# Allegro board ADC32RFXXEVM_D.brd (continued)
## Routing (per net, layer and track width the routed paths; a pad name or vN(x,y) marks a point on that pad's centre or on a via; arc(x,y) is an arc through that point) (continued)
V1: length 33
  TOP w0.229: U32.1 18.38,45.85 v1(18.24,46) ; U33.1 v2(18.39,42.65)
  L4_SIG w0.127: v2(18.39,42.65) 18.65,42.65 18.92,42.92 18.92,43.76 18.49,44.2 18.49,45.75 v1(18.24,46) 18.16,46 15.11,49.05 15.11,51.91 23.12,59.92 23.62,59.92 24.05,60.35 v1(24.13,60.35) 24.18,60.35 24.69,60.86 25.7,60.86 25.96,61.11 25.96,64.74 26.37,65.15 26.77,65.15 JP3.1
V2: length 32.7
  TOP w0.203: U33.5 18.03,40.59 v1(17.88,40.44)
  TOP w0.229: U32.5 v2(18.03,42.95)
  L4_SIG w0.127: JP3.3 27.05,60.35 v1(25.27,60.35) 24.92,60.35 16.79,52.22 16.79,51.26 17.63,50.42 17.63,47.73 19.27,46.09 19.27,45.02 19.62,44.66 19.62,43.37 19.38,43.13 19.38,42.04 17.88,40.54 v1(17.88,40.44) 17.65,40.67 17.65,42.27 18.03,42.65 v2(18.03,42.95)
A_IN_M: length 14.8
  TOP w0.483: J2.1 3.82,22.57 arc(4.57,22.42) 5.21,21.99 5.66,21.54 arc(6.4,21.05) 7.26,20.88 11.6,20.88 arc(13.88,21.33) C415.1
A_IN_P: length 14.8
  TOP w0.483: C414.1 13.66,24.79 13.17,24.79 arc(12.57,24.91) 12.06,25.25 5.09,32.22 arc(4.53,32.6) 3.87,32.73 J1.1
ADC_CLK: length 4.3
  BOTTOM w0.483: J5.1 3.77,42.89 arc(4.26,42.99) 4.68,43.27 4.83,43.41 arc(5.37,43.78) C28.1
ADC_CLKM: length 3.1
  TOP w0.229: U1.28 22.07,42.49 22.01,42.55 20.59,42.55 R26.1
  TOP w0.305: C430.2 20.33,42.29 R26.1
ADC_CLKP: length 3.1
  TOP w0.229: U1.27 22.07,42.99 22.01,42.93 20.49,42.93 R26.2
  TOP w0.305: R26.2 20.36,43.05 C429.2
ADC_SCLK: length 45.1
  TOP w0.127: v1(30.27,50.79) 30.27,50.3 30.17,50.2 30.17,50.01 30.16,50 30.16,48.97 30.14,48.94 30.14,48.65 29.44,47.96 29.44,47.69 U1.6
  L4_SIG w0.127: v1(30.27,50.79) 29.56,50.79 29.18,50.42 26.95,50.42 26.48,49.95 26.48,48.28 26.98,47.78 26.98,40.07 26.53,39.61 26.33,39.61 25.82,39.11 25.82,38.59 25.91,38.5 25.91,35.28 27.28,33.91 31.86,33.91 33.25,32.51 34.16,32.51 35.41,31.27 35.41,30.84 37.54,28.7 37.54,26.75 39.78,24.51 v1(39.78,24.36)
  BOTTOM w0.127: v1(39.78,24.36) 39.8,24.33 U29.2
ADC_SDIO: length 39.6
  TOP w0.127: U1.5 29.89,47.92 30.39,48.43 30.39,48.84 30.42,48.86 30.42,49.9 30.42,49.9 30.42,50.09 v1(31.35,51.02)
  L4_SIG w0.127: v1(43.21,25.35) 43.21,26.06 40.64,28.63 39.57,28.63 35.53,32.66 35.53,33.35 30.66,38.23 30.12,38.23 29.77,38.58 29.77,47.19 30.33,47.75 30.33,50 v1(31.35,51.02)
  BOTTOM w0.127: v1(43.21,25.35) 43.21,24.08 42.81,23.68 U29.3
ADC_SDO: length 43.5
  TOP w0.127: v1(26.92,48.46) 26.89,48.42 U1.11
  L4_SIG w0.127: v1(33.07,48.13) 32.81,48.13 32.8,48.15 32.17,48.15 31.04,47.02 31.04,38.48 33.53,35.99 34.04,35.99 39.57,30.45 40.03,30.45 43.71,26.77 43.71,25.12 42.11,23.52 v1(40.39,23.52)
  BOTTOM w0.127: v1(33.07,48.13) 32.81,48.13 32.8,48.15 32.02,48.15 31.48,47.61 27.7,47.61 26.92,48.39 v1(26.92,48.46) ; U29.4 40.88,23.03 v1(40.39,23.52)
ADC_SEN: length 39.4
  TOP w0.127: U1.7 28.89,47.86 29.71,48.68 v1(29.73,49.15)
  L4_SIG w0.127: v1(29.73,49.15) 29.47,48.89 29.47,48.21 28.37,47.12 28.37,38.58 28.78,38.18 29.64,38.18 30.07,37.74 30.53,37.74 32.35,35.93 32.35,34.84 35.9,31.29 35.9,30.88 36.58,30.2 37.53,30.2 38.46,29.27 38.46,28.53 38.05,28.12 38.05,26.72 40.18,24.59 40.18,24.58 40.22,24.54 40.22,24.17 39.96,23.91 39,23.91 v1(38.79,24.13)
  BOTTOM w0.127: v1(38.79,24.13) 40.54,22.38 U29.5
AIN+: length 4.1
  TOP w0.483: C1.1 T2.3 20.61,31.39 T1.1 18.83,29.65 R1.2
AIN-: length 4.1
  TOP w0.483: R11.2 T1.3 20.66,27.89 T2.1 C6.1
AINM: length 6
  TOP w0.635: 25.26,36.39 25.26,35.35 arc(25.23,34.79) 25.15,34.23 arc(24.96,33.92) 24.6,33.82 arc(24.38,33.9) 24.21,34.06 arc(23.85,34.36) 23.4,34.23 T2.4 22.29,33.11 C1.2
AINP: length 5.9
  TOP w0.635: C6.2 24.1,31.33 T2.6 25.05,32.28 arc(25.85,33.48) 26.13,34.89 26.13,36.53
B_IN_M: length 14.7
  TOP w0.483: J4.1 4.15,53.05 arc(4.6,53.14) 4.98,53.39 11.56,59.97 arc(12.34,60.5) 13.27,60.68 13.69,60.68 C417.1
B_IN_P: length 14.7
  TOP w0.483: C416.1 14.74,63.88 arc(14.17,64.26) 13.5,64.39 6.81,64.39 arc(6.2,64.27) 5.67,63.92 5.37,63.61 arc(4.92,63.31) 4.39,63.21 J3.1
BIN+: length 4.1
  TOP w0.483: C12.1 T4.1 T3.3 18.3,56.35 R23.2
BIN-: length 3.3
  TOP w0.483: T4.3 T3.1 R13.2
BINM: length 5.9
  TOP w0.635: T4.6 23.59,51.07 24.07,51.07 24.42,51.42 arc(25.09,51.49) 25.45,50.92 25.45,49.2
  TOP w0.762: C12.2 T4.6
BINP: length 6
  TOP w0.635: T4.4 24.65,53.58 25.71,52.52 arc(26.18,51.82) 26.34,51.01 26.34,49.05
  TOP w0.762: C7.2 T4.4
CE: length 18.4
  L6_PWR w0.305: JP2.2 34.47,64.74 38.48,64.74 39.57,63.65 48.62,63.65 v1(48.67,63.7)
  BOTTOM w0.305: v1(48.67,63.7) 48.66,63.69 U30.1
CLK-IN: length 4.2
  BOTTOM w0.483: R56.1 T6.6 62.58,62.81 R59.1 R57.2
CLK_LAO_0M: length 39.8
  BOTTOM w0.165: 123.44,52.01 123.51,52.07 127.47,52.07 127.64,51.9 127.64,51.56
  BOTTOM w0.203: 90.47,52.66 90.44,52.69 R79.2
  BOTTOM w0.229: 90.47,52.66 91.16,51.97 112.69,51.97 114.52,50.14 116.48,50.14 118.35,52.01 123.44,52.01
CLK_LAO_0P: length 39.8
  BOTTOM w0.165: 123.44,52.39 123.51,52.32 127.47,52.32 127.64,52.49 127.64,52.83
  BOTTOM w0.203: R75.2 90.69,52.98 90.73,52.94
  BOTTOM w0.229: 123.44,52.39 118.19,52.39 116.33,50.52 114.68,50.52 112.85,52.35 93.12,52.35 92.76,52.7 92.29,52.7 91.93,52.35 91.32,52.35 90.73,52.94
CLKIN1_N: length 6.5
  BOTTOM w0.229: C74.2 72.79,64.64 72.8,64.66 72.86,64.66 72.89,64.69 73.58,64.69 C75.2 73.71,64.72 74.47,63.96 76.65,63.96 77.1,63.51 77.1,62.87 77.16,62.81 U3.35
CLKIN1_P: length 6.1
  BOTTOM w0.229: U3.34 76.66,62.81 76.72,62.87 76.72,63.35 76.49,63.58 74.31,63.58 73.62,64.27 72.96,64.27 72.77,64.08 C73.2
CLKINN: length 4.4
  BOTTOM w0.483: C74.1 70.51,64.64 R60.2 69.8,65.35 T6.3
CLKINP: length 5.4
  BOTTOM w0.483: R56.2 T6.1 69.44,62.81 R60.1 70.43,63.8 R55.1 71.4,63.88 C73.1
CLKLA_0M: length 6.3
  BOTTOM w0.203: 89.67,53.12 89.62,53.12 89.05,53.7
  BOTTOM w0.229: U3.63 85.37,54.1 85.43,54.16 85.95,54.16 86.1,54.31 87.4,54.31 87.73,53.98 88.08,53.98 88.42,54.31 88.85,54.31 89.08,54.07 89.08,53.73 89.05,53.7
CLKLA_0P: length 6.3
  BOTTOM w0.203: R77.1 90.26,53.78 R75.1
  BOTTOM w0.229: R77.1 89.66,54.31 89.38,54.31 89.01,54.69 85.94,54.69 85.8,54.54 85.43,54.54 85.37,54.6 U3.62
CLKM: length 53.5
  TOP w0.229: v1(36.3,56.41) 36.3,58.18 34.75,59.73 33.93,59.73 33.71,59.5 v1(33.71,58.93)
  BOTTOM w0.229: v1(36.3,56.41) 36.39,56.41 36.93,55.87 36.93,54.71 37.2,54.44 37.76,54.44 37.97,54.24 37.97,53.68 43.55,48.09 43.83,48.09 43.97,48.23 44.25,48.23 44.45,48.03 44.45,47.74 44.32,47.61 44.32,47.33 45.09,46.56 73.42,46.56 73.62,46.76 73.62,46.97 73.82,47.17 74.11,47.17 74.31,46.97 74.31,46.76 74.51,46.56 75.44,46.56 75.86,46.98 75.86,47.83 75.67,48.02 C9.2
CLKP: length 53.5
  TOP w0.229: v1(36.42,55.68) 36.77,56.02 36.77,56.61 36.68,56.7 36.68,58.34 34.91,60.11 33.93,60.11 33.71,60.34 v1(33.73,60.91)
  BOTTOM w0.229: v1(36.42,55.68) 36.55,55.55 36.55,54.55 44.93,46.18 75.6,46.18 76.24,46.82 76.24,47.83 76.43,48.02 C8.2
CP1: length 37.8
  L4_SIG w0.305: v1(104.6,62.76) 104.34,62.76 102.84,64.26 96.6,64.26 95.61,65.25 94.39,65.25 93.8,64.67 82.91,64.67 80.98,62.74 78.49,62.74 77.57,63.65 74.76,63.65 74.22,63.11 74.22,61.62 73.71,61.11 v1(73.25,61.11)
  BOTTOM w0.305: U3.32 73.26,61.11 v1(73.25,61.11)
  vias: v1(105.36,62.76)
CP2: length 5.6
  BOTTOM w0.305: U3.46 82.66,62.46 82.97,62.76 85.01,62.76 85.37,62.41 C72.1 87.35,62.41 C71.1
CPOUT: length 15
  TOP w0.229: v1(47.14,57.35) 50.72,60.93 v1(50.72,66.32)
  BOTTOM w0.229: v1(50.72,66.32) 50.67,66.37 C395.1 49.15,66.37 R182.1 ; U30.12 45.16,57.64 45.44,57.35 v1(47.14,57.35)
DA0_M: length 2.8
  TOP w0.229: U1.62 32.59,41.94 33.49,41.94 33.62,41.81 35.04,41.81 C14.1
DA0_P: length 2.8
  TOP w0.229: C13.1 34.99,41.43 33.46,41.43 33.33,41.55 32.6,41.55 U1.61
DA0M: length 106.8
  TOP w0.229: v1(133.99,43.94) 133.99,44.07 134.29,44.37 134.78,44.37 135.23,44.83 135.23,45.5 134.52,46.2 130.88,46.2 126.31,41.63 124.66,41.63 121.43,38.4 43.66,38.4 40.28,41.78 36,41.78 C14.2
DA0P: length 106.8
  TOP w0.229: C13.2 36,41.4 40.13,41.4 43.5,38.02 121.59,38.02 124.82,41.25 126.47,41.25 127.15,41.93 127.61,41.93 127.91,42.24 127.91,42.7 129.79,44.57 130.07,44.57 130.29,44.34 130.58,44.34 130.78,44.55 130.78,44.83 130.55,45.05 130.55,45.34 131.04,45.82 134.37,45.82 134.85,45.34 134.85,44.98 134.62,44.75 134.29,44.75 133.99,45.06 v1(133.99,45.21)
DA1_M: length 3.1
  TOP w0.229: U1.59 32.79,40.49 32.85,40.43 33.79,40.43 34.58,39.64 35.03,39.64 C16.1
DA1_P: length 3.1
  TOP w0.229: C15.1 35,39.26 34.42,39.26 33.63,40.05 32.83,40.05 32.77,39.99 U1.58
DA1M: length 108.3
  TOP w0.229: C16.2 36,39.62 39.12,39.62 42.45,36.3 122.17,36.3 125.39,39.52 127.99,39.52 131.69,43.23 134.18,43.23 134.74,43.79 136.15,43.79 136.6,43.34 136.6,42.33 136.15,41.88 135.73,41.88 v1(135.25,41.4)
DA1P: length 108.2
  TOP w0.229: v1(135.25,42.67) 135.67,42.26 135.99,42.26 136.22,42.49 136.22,43.18 135.99,43.41 134.9,43.41 134.34,42.85 131.85,42.85 131.57,42.57 131.57,42.28 131.67,42.19 131.67,41.9 131.47,41.7 131.18,41.7 131.09,41.8 130.8,41.8 129.18,40.18 129.18,39.9 129.29,39.79 129.29,39.5 129.09,39.3 128.81,39.3 128.7,39.41 128.41,39.41 128.14,39.14 125.55,39.14 122.33,35.92 42.29,35.92 38.96,39.24 36,39.24 C15.2
DA2_M: length 3.3
  TOP w0.229: C18.1 35.06,37.51 34.81,37.51 33.39,38.93 32.85,38.93 32.8,38.99 U1.56
DA2_P: length 3.4
  TOP w0.229: C17.1 34.99,37.11 34.67,37.11 33.23,38.55 32.78,38.55 32.72,38.49 U1.55
DA2M: length 106.4
  TOP w0.229: v1(133.99,38.86) 133.99,39.02 134.28,39.32 134.69,39.32 135.15,39.77 135.15,40.55 134.27,41.43 132.2,41.43 128.06,37.29 125.75,37.29 122.78,34.32 41.36,34.32 38.21,37.47 36,37.47 C18.2
DA2P: length 106.4
  TOP w0.229: C17.2 36,37.08 38.05,37.08 41.2,33.93 122.94,33.93 125.91,36.91 126.45,36.91 126.76,36.6 127.14,36.6 127.45,36.91 128.22,36.91 130.98,39.67 131.27,39.67 131.5,39.43 131.79,39.43 131.99,39.64 131.99,39.92 131.75,40.16 131.75,40.44 132.36,41.05 134.11,41.05 134.77,40.39 134.77,39.93 134.54,39.7 134.21,39.7 133.99,39.93 v1(133.99,40.13)
DA3_M: length 5.3
  TOP w0.229: C20.1 35.01,35.31 34.09,35.31 33.66,35.74 33.66,36.02 33.79,36.15 33.79,36.47 33.56,36.7 32.69,36.7 31.84,37.56 31.84,37.79 U1.54
DA3_P: length 5.3
  TOP w0.229: U1.53 31.46,37.77 31.46,37.4 33.93,34.92 35.01,34.92 C19.1
DA3M: length 107.2
  TOP w0.229: C20.2 36,35.31 37.11,35.31 40.24,32.18 130.72,32.18 131.08,32.54 131.41,32.54 131.76,32.18 133.43,32.18 135.28,34.04 135.28,34.32 135.07,34.53 135.07,34.82 135.27,35.02 135.56,35.02 135.77,34.81 136.05,34.81 136.4,35.15 136.4,36.54 136.17,36.77 135.7,36.77 v1(135.25,36.32)
DA3P: length 107.3
  TOP w0.229: C19.2 36,34.92 36.96,34.92 40.08,31.8 133.58,31.8 136.78,35 136.78,36.7 136.33,37.15 135.7,37.15 v1(135.25,37.59)
DB0_M: length 2.8
  TOP w0.229: U1.65 32.84,43.49 32.9,43.54 35.03,43.54 C22.1
DB0_P: length 2.8
  TOP w0.229: U1.66 32.85,43.99 32.91,43.93 35,43.93 C21.1
DB0M: length 103.9
  TOP w0.229: v1(135.25,46.48) 134.8,46.94 129.59,46.94 126.03,43.38 123.98,43.38 120.73,40.13 44.45,40.13 41.02,43.56 36,43.56 C22.2
DB0P: length 103.9
  TOP w0.229: v1(135.25,47.75) 134.82,47.32 129.43,47.32 125.88,43.76 123.82,43.76 120.57,40.51 44.61,40.51 41.18,43.94 36,43.94 C21.2
DB1_M: length 3.1
  TOP w0.229: U1.68 32.84,44.99 32.9,45.05 33.74,45.05 34.42,45.72 35.01,45.72 C24.1
DB1_P: length 3.1
  TOP w0.229: U1.69 32.82,45.49 32.88,45.43 33.59,45.43 34.26,46.1 35.01,46.1 C23.1
DB1M: length 102.8
  TOP w0.229: v1(132.72,51.56) 132.72,51.64 132.33,52.02 129.72,52.02 119.86,42.16 45.49,42.16 41.94,45.72 36,45.72 C24.2
DB1P: length 102.7
  TOP w0.229: C23.2 36,46.1 42.09,46.1 45.65,42.55 119.7,42.55 129.56,52.4 132.33,52.4 132.72,52.78 v1(132.72,52.83)
DB2_M: length 3.3
  TOP w0.229: C27.1 35.04,47.85 34.6,47.85 33.3,46.55 32.84,46.55 32.77,46.49 U1.71
DB2_P: length 3.3
  TOP w0.229: C26.1 34.99,48.23 34.44,48.23 33.14,46.94 32.82,46.94 32.77,46.99 U1.72
DB2M: length 106.2
  TOP w0.229: v1(135.25,51.56) 135.25,51.74 134.95,52.04 134.09,52.04 133.48,52.65 133.48,53.14 132.89,53.72 128.81,53.72 119.39,44.3 46.74,44.3 43.15,47.88 36,47.88 C27.2
DB2P: length 106.2
  TOP w0.229: C26.2 36,48.26 43.31,48.26 46.89,44.68 119.23,44.68 128.65,54.1 133.05,54.1 133.86,53.29 133.86,52.81 134.24,52.43 135.03,52.43 135.25,52.65 v1(135.25,52.83)
DB3_M: length 5.3
  TOP w0.229: C31.1 35.01,50.04 33.91,50.04 33.66,49.78 33.66,49.38 33.76,49.28 33.76,48.94 33.48,48.67 32.54,48.67 31.83,47.96 31.83,47.69 U1.1
DB3_P: length 5.3
  TOP w0.229: C30.1 35.01,50.42 33.75,50.42 31.45,48.11 31.45,47.7 U1.2
DB3M: length 106
  TOP w0.229: v1(135.25,56.64) 135.25,56.82 134.98,57.1 131.96,57.1 131.68,56.82 129.01,56.82 118.36,46.18 47.9,46.18 44.02,50.06 36.03,50.06 C31.2
DB3P: length 105.9
  TOP w0.229: v1(135.25,57.91) 135.25,57.71 135.03,57.48 131.8,57.48 131.52,57.2 128.85,57.2 118.21,46.56 48.06,46.56 44.18,50.44 35.98,50.44 C30.2
DCLKOUT10N: length 4.2
  BOTTOM w0.229: C171.1 88.09,58.14 87.73,58.14 R151.1 87.15,58.17 84.96,58.17 84.9,58.11 U3.55
DCLKOUT10P: length 4.1
  BOTTOM w0.229: U3.54 84.9,58.61 84.99,58.52 87.2,58.52 R152.1 87.73,58.5 88.09,58.5 C170.1
FMC_CTRL1: length 175.1
  L4_SIG w0.127: v1(132.72,27.43) 132.72,27.28 132.16,26.72 123.47,26.72 122.68,25.93 122.68,7.54 120.68,5.54 119.2,5.54 113.84,10.9 98.91,10.9 98.02,10.01 97.35,10.01 97.33,10.02 85.38,10.02 85.26,10.15 84.45,10.15 79.08,15.52 71.65,15.52 71.01,16.16 69.41,16.16 69.1,16.47 66.03,16.47 65.56,16 54.64,16 53.94,16.69 50.5,16.69 48.74,14.94 31.93,14.94 29.46,17.4 29.46,19.41 28.79,20.08 28.79,25.36 26.29,27.86 26.29,31.45 23.16,34.57 22.46,34.57 21.68,35.35 21.68,38.79 23.48,40.6 23.9,40.6 24.19,40.89 24.19,44.26 23.9,44.55 23.31,44.55 22.7,45.16 22.43,45.16 18.58,49.01 18.58,49.06 18.49,49.15 18.49,52.12 v1(18.06,52.55)
  BOTTOM w0.229: R165.1 v1(18.06,52.55)
FMC_CTRL2: length 172.7
  L4_SIG w0.127: v1(17.25,51.74) 18.06,50.93 18.06,47.98 19.96,46.08 19.96,40.92 18.75,39.7 18.75,35.23 19.31,34.66 21.65,34.66 24.47,31.84 25.1,31.84 25.84,31.1 25.84,26.73 28.07,24.5 28.07,22.39 27.84,22.15 27.84,18.31 31.6,14.55 52.12,14.55 52.57,15 79,15 84.21,9.79 84.54,9.79 85.3,9.03 102.73,9.03 104.06,10.36 113.56,10.36 118.97,4.95 120.8,4.95 123.16,7.31 123.16,24.35 124.23,25.43 131.98,25.43 v1(132.72,26.16)
  BOTTOM w0.229: 18.16,50.83 v1(17.25,51.74)
FPGA_JESD_CLKM: length 55.2
  BOTTOM w0.165: 123.44,50.75 123.5,50.81 129.22,50.81 129.66,51.25 129.66,54.32 129.95,54.61 131.28,54.61 131.44,54.44 J10.D5
  BOTTOM w0.229: 123.44,50.75 122.97,50.75 118.39,46.18 84.89,46.18 83.49,47.57 83.49,48.25 C69.2
FPGA_JESD_CLKP: length 55.2
  BOTTOM w0.165: 123.44,51.13 123.46,51.13 123.53,51.06 129.11,51.06 129.41,51.35 129.41,54.43 129.84,54.86 131.28,54.86 131.44,55.03 J10.D4
  BOTTOM w0.229: 123.44,51.13 122.81,51.13 121.92,50.25 121.62,50.25 121.26,49.89 121.26,49.58 118.24,46.56 86.85,46.56 86.65,46.76 86.65,46.81 86.45,47.02 86.16,47.02 85.96,46.81 85.96,46.76 85.76,46.56 85.04,46.56 83.87,47.73 83.87,48.26 C67.2
FPGA_JESD_SYSREFM: length 50.6
  BOTTOM w0.165: 123.44,48.2 123.46,48.2 123.53,48.26 127.47,48.26 127.64,48.09 127.64,47.75
  BOTTOM w0.203: R49.2 81.21,47.46 81.21,46.47 83.39,44.3 119.35,44.3 123.25,48.2
  BOTTOM w0.229: 123.44,48.2 123.25,48.2
FPGA_JESD_SYSREFP: length 50.6
  BOTTOM w0.165: 123.44,48.58 123.46,48.58 123.53,48.52 127.13,48.52 127.64,49.02
  BOTTOM w0.203: R48.2 81.57,47.46 81.57,46.62 81.91,46.27 82.17,46.27 82.27,46.38 82.52,46.38 82.7,46.2 82.7,45.95 82.6,45.84 82.6,45.59 83.54,44.65 117.99,44.65 118.19,44.86 118.65,44.86 118.85,44.65 119.21,44.65 122.89,48.33 122.89,48.35 123.1,48.57 123.2,48.57 123.22,48.58 123.25,48.58
  BOTTOM w0.229: 123.44,48.58 123.25,48.58
GPIO1: length 49.9
  TOP w0.127: v1(22.02,47.52) 22.56,46.99 U1.19
  L4_SIG w0.127: TP3.1 53.11,31.8 53.11,32.71 49.88,35.94 49.25,35.94 41.33,43.87 40.79,43.87 34.34,50.32 34.01,50.32 32.79,51.54 27.68,51.54 27.5,51.36 26.75,51.36 25.1,49.71 25.1,48.49 24.13,47.52 v1(22.02,47.52)
GPIO2: length 30.3
  TOP w0.127: U1.63 v1(33.77,42.49)
  L4_SIG w0.127: v1(33.77,42.49) 33.77,42.81 34.26,43.31 41.15,43.31 49.1,35.36 49.1,35.03 52.81,31.32 TP7.1
GTXCLKM: length 4.1
  BOTTOM w0.203: 83.27,49.9 83.5,50.12 83.5,51.07 83.24,51.33 83.24,51.87 83.16,51.94 U3.2 ; C69.1 83.3,49.11 ; 83.3,49.82 R52.1
  BOTTOM w0.229: 83.27,49.9 83.3,49.87 83.3,49.11
GTXCLKP: length 4.1
  BOTTOM w0.203: 84.06,49.82 R53.1 ; C67.1 84.06,49.11 ; U3.1 83.66,51.94 83.59,51.87 83.59,51.48 83.86,51.22 83.86,50.12 84.08,49.9
  BOTTOM w0.229: 84.08,49.9 84.06,49.87 84.06,49.11
JESD_SYSREFM: length 5.2
  BOTTOM w0.203: U3.4 82.16,51.94 82.24,51.87 82.24,51.58 81.23,50.58 81.23,49.35 80.99,49.11 ; R49.1 81.01,48.32 ; 81.01,49.03 R50.1
  BOTTOM w0.229: 80.99,49.11 81.01,49.08 81.01,48.32
JESD_SYSREFP: length 5.2
  BOTTOM w0.203: 81.8,49.11 81.58,49.32 81.58,50.43 82.59,51.43 82.59,51.87 82.66,51.94 U3.3 ; 81.77,49.03 R51.1 ; R48.1 81.77,48.32
  BOTTOM w0.229: 81.8,49.11 81.77,49.08 81.77,48.32
LMK LOCKED:
  vias: v1(55.78,55.65)
LMK_CLKIN: length 4.8
  BOTTOM w0.483: R57.1 R58.1 56.16,62.79 J7.1
LMK_CSB: length 78.9
  L4_SIG w0.127: v1(73.91,50.8) 74.42,50.29 74.42,47.32 74.14,47.04 74.14,40.03 75.22,38.95 75.22,26.1 75.51,25.81 75.51,24.05 71.48,20.02 46.96,20.02 46.44,19.49 44.51,19.49 44.13,19.88 35.31,19.88 34.9,19.47 v1(32.73,19.47)
  BOTTOM w0.127: v1(73.91,50.8) 73.6,51.12 73.6,53.78 73.92,54.1 U3.18 ; U5.6 v1(32.73,19.47)
LMK_SCLK: length 111.9
  TOP w0.127: v1(37.31,25.37) 37.31,24.92 36.7,24.31 34.82,24.31 33.23,22.72 v1(32.78,22.72)
  L4_SIG w0.127: v1(43.13,57.23) 43.13,56.67 43.54,56.26 45.09,56.26 46.52,54.83 46.52,54.43 46.78,54.17 47.28,54.17 47.89,53.56 48.94,53.56 49.22,53.28 49.59,53.28 49.73,53.42 52.22,53.42 54.84,50.8 v1(72.03,50.8) 72.03,50.27 71.49,49.72 71.49,27.52 69.65,25.68 54.71,25.68 50.24,21.21 46.36,21.21 45.9,21.67 39.24,21.67 37.31,23.6 v1(37.31,25.37)
  BOTTOM w0.127: U3.19 74.06,54.6 73.23,53.77 73.23,51.44 72.67,50.88 72.11,50.88 v1(72.03,50.8) ; U5.1 v1(32.78,22.72) ; v1(43.13,57.23) 43.16,57.26 U30.16 ; U29.13 36.78,24.33 37.31,24.87 v1(37.31,25.37)
LMK_SDIO: length 116.7
  L4_SIG w0.127: v1(42.65,57.63) 42.65,58.24 43.71,59.31 44.86,59.31 45.29,58.88 45.29,57.91 46.37,56.83 46.37,55.66 46.98,55.05 47.15,55.05 47.43,54.77 47.43,54.55 48.06,53.92 48.98,53.92 49.22,54.17 49.59,54.17 49.83,53.92 52.32,53.92 54.89,51.36 v1(72.47,51.36) 72.54,51.28 72.54,49.96 71.98,49.4 71.98,38 72.47,37.52 72.47,35.94 72.09,35.56 72.09,27.43 69.82,25.17 54.86,25.17 50.5,20.8 46.09,20.8 45.78,21.12 42.81,21.12 42.24,20.55 40.56,20.55 40.31,20.8 35.38,20.8 34.7,20.12 v1(33.5,20.12) 33.5,22.99 34.2,23.68 v1(34.84,23.68)
  BOTTOM w0.127: U30.17 v1(42.65,57.63) ; U3.20 73.95,55.1 72.92,54.08 72.92,51.82 v1(72.47,51.36) ; U5.5 v1(33.5,20.12) ; U29.12 v1(34.84,23.68)
LMK_SDO: length 82.9
  TOP w0.127: v2(81.66,52.78) 81.66,52.45 80.29,51.08 75.29,51.08 v1(74.94,50.74)
  L4_SIG w0.127: v1(74.94,50.74) 75.67,50.01 75.67,43.63 75.68,43.62 75.68,26.56 75.95,26.29 75.95,23.67 71.75,19.48 47.35,19.48 46.89,19.02 44.2,19.02 43.73,19.49 41.73,19.49 41.59,19.35 35.86,19.35 v1(33.38,16.87)
  BOTTOM w0.127: U5.10 v1(33.38,16.87)
LMX_CLKB: length 23.1
  BOTTOM w0.483: R191.2 61.49,59.44 arc(61.4,58.97) 61.14,58.58 arc(60.82,58.37) 60.45,58.29 54.13,58.29 arc(52.86,58.04) 51.78,57.32 48.92,54.45 arc(48.13,53.93) 47.21,53.75 R192.2 43.38,54.38 C412.2
LMX_CLKM: length 30.1
  TOP w0.229: v1(17.02,44.98) 17.68,44.98 U32.3
  BOTTOM w0.229: v1(17.02,44.98) 17.02,44.07 16.79,43.84 16.21,43.84 15.44,44.6 15.44,44.88 15.59,45.02 15.59,45.35 15.44,45.49 15.44,45.75 15.72,46.02 15.88,46.02 16.21,45.68 16.37,45.68 16.5,45.81 16.5,46.14 16.33,46.31 16.33,46.63 16.74,47.04 19.2,47.04 31.14,58.98 31.42,58.98 31.69,59.25 31.69,59.52 31.89,59.73 33.12,59.73 33.32,59.54 C410.2
LMX_CLKP: length 30.1
  TOP w0.229: v1(17.02,42.32) 17.68,42.32 U33.3
  BOTTOM w0.229: C431.1 33.32,60.3 33.12,60.11 31.73,60.11 19.04,47.42 16.58,47.42 15.06,45.9 15.06,44.44 16.05,43.46 16.79,43.46 17.02,43.23 v1(17.02,42.32)
LMX_CSB: length 71.3
  L4_SIG w0.127: v1(30.05,17.53) 29.87,17.7 29.87,19.63 30.52,20.29 30.52,24.01 30.07,24.46 30.07,25.98 27.74,28.32 27.74,32.87 25.5,35.1 25.5,39.22 25.7,39.42 25.7,45.52 25.1,46.13 22.5,46.13 19.2,49.43 19.2,50.36 20.09,51.26 21.21,51.26 21.67,50.8 22.17,50.8 24.89,53.52 25.35,53.52 26.4,54.57 27.78,54.57 28.07,54.28 31.04,54.28 31.43,54.67 32.3,54.67 32.49,54.48 36.65,54.48 37.17,55 37.17,55.3 37.43,55.56 38.04,55.56 38.61,56.13 38.61,56.58 37.9,57.3 37.9,57.99 39.32,59.41 v1(39.32,61.32)
  BOTTOM w0.127: U5.9 v1(30.05,17.53) ; U30.24 39.71,60.69 39.32,61.09 v1(39.32,61.32)
LMX_OSCM: length 39.6
  TOP w0.229: v1(50.4,57.81) 50.68,58.09 64.95,58.09 72.95,66.09 74.85,66.09 v1(75.08,65.86)
  BOTTOM w0.203: v1(75.08,65.86) 75.39,66.17 75.79,66.17 76.4,66.78 78.12,66.78 78.29,66.6 78.29,66.45 78.47,66.27 78.73,66.27 78.9,66.45 78.9,66.6 79.08,66.78 79.44,66.78 79.72,66.5 79.72,65.8 C418.2 ; U30.9 47.27,59.69 47.32,59.75
  BOTTOM w0.229: v1(50.4,57.81) 50.14,58.06 49.43,58.06 47.75,59.74 47.33,59.74 47.32,59.75
LMX_OSCP: length 39.6
  TOP w0.229: v1(75.08,66.78) 74.77,66.47 72.79,66.47 64.79,58.47 50.66,58.47 v1(50.4,58.73)
  BOTTOM w0.203: v1(75.08,66.78) 75.34,66.52 75.64,66.52 76.25,67.13 79.59,67.13 80.07,66.64 80.07,65.8 C419.2 ; U30.8 47.27,60.19 47.34,60.12 47.49,60.12 47.49,60.12
  BOTTOM w0.229: 47.49,60.12 47.91,60.12 49.59,58.45 50.12,58.45 v1(50.4,58.73)
LMX_SDO: length 59
  L4_SIG w0.127: v1(38.07,56.36) 37.59,56.36 36.87,55.64 36.87,55.26 36.5,54.89 32.74,54.89 32.49,55.14 31.32,55.14 30.89,54.71 28.07,54.71 27.89,54.89 26.24,54.89 25.25,53.9 24.66,53.9 22.99,52.22 20.47,52.22 18.88,50.63 18.88,49.21 22.4,45.69 22.6,45.69 23.42,44.87 24,44.87 24.49,44.38 24.49,40.21 23.9,39.61 23.66,39.61 22.76,38.71 22.76,35.49 23.22,35.03 23.65,35.03 27.28,31.39 27.28,28.35 29.72,25.91 29.72,24.05 30.08,23.69 v1(30.08,22.07)
  BOTTOM w0.127: U5.2 v1(30.08,22.07)
Net_59:
  vias: v3(126.36,21.08)
Net_101:
  vias: v1(126.36,40.13)
Net_102:
  vias: v1(127.64,40.13)
Net_216:
  vias: v3(135.25,31.24)
Net_217:
  vias: v3(135.25,27.43)
Net_218:
  vias: v3(135.25,26.16)
Net_219:
  vias: v3(135.25,22.35)
Net_220:
  vias: v3(135.25,21.08)
Net_221:
  vias: v3(135.25,17.27)
Net_222:
  vias: v3(135.25,16)
Net_223:
  vias: v3(135.25,12.19)
Net_224:
  vias: v3(135.25,10.92)
Net_225:
  vias: v3(133.99,59.18)
Net_227:
  vias: v3(133.99,33.78)
Net_228:
  vias: v3(133.99,29.97)
Net_229:
  vias: v3(133.99,28.7)
Net_230:
  vias: v3(133.99,24.89)
Net_231:
  vias: v3(133.99,23.62)
Net_232:
  vias: v3(133.99,19.81)
Net_233:
  vias: v3(133.99,18.54)
Net_234:
  vias: v3(133.99,14.73)
Net_235:
  vias: v3(133.99,13.46)
Net_236:
  vias: v3(133.99,55.37)
Net_237:
  vias: v3(133.99,9.65)
Net_238:
  vias: v3(133.99,54.1)
Net_239:
  vias: v3(133.99,50.29)
Net_240:
  vias: v3(133.99,49.02)
Net_243:
  vias: v3(132.72,36.32)
Net_246:
  vias: v3(132.72,31.24)
Net_248:
  vias: v3(132.72,22.35)
Net_249:
  vias: v3(132.72,21.08)
Net_250:
  vias: v3(132.72,17.27)
Net_251:
  vias: v3(132.72,16)
Net_252:
  vias: v3(132.72,13.46)
Net_253:
  vias: v3(132.72,10.92)
Net_254:
  vias: v3(131.44,59.18)
Net_256:
  vias: v3(131.44,45.21)
Net_260:
  vias: v3(131.44,33.78)
Net_261:
  vias: v3(131.44,31.24)
Net_262:
  vias: v3(131.44,29.97)
Net_263:
  vias: v3(131.44,27.43)
Net_264:
  vias: v3(131.44,26.16)
Net_265:
  vias: v3(131.44,23.62)
Net_266:
  vias: v3(131.44,22.35)
Net_267:
  vias: v3(131.44,21.08)
Net_268:
  vias: v3(131.44,19.81)
Net_269:
  vias: v3(131.44,18.54)
Net_270:
  vias: v3(131.44,17.27)
Net_271:
  vias: v3(131.44,16)
Net_272:
  vias: v3(131.44,14.73)
Net_273:
  vias: v3(131.44,12.19)
Net_274:
  vias: v3(131.44,9.65)
Net_275:
  vias: v3(131.44,50.29)
Net_276:
  vias: v3(131.44,49.02)
Net_282:
  vias: v3(130.18,37.59)
Net_285:
  vias: v3(130.18,33.78)
Net_287:
  vias: v3(130.18,29.97)
Net_288:
  vias: v3(130.18,28.7)
Net_289:
  vias: v3(130.18,26.16)
Net_290:
  vias: v3(130.18,24.89)
Net_292:
  vias: v3(130.18,22.35)
Net_293:
  vias: v3(130.18,21.08)
Net_294:
  vias: v3(130.18,18.54)
Net_295:
  vias: v3(130.18,17.27)
Net_296:
  vias: v3(130.18,14.73)
Net_297:
  vias: v3(130.18,13.46)
Net_298:
  vias: v3(130.18,10.92)
Net_301:
  vias: v3(130.18,49.02)
Net_302:
  vias: v3(128.91,59.18)
Net_303:
  vias: v3(128.91,47.75)
Net_306:
  vias: v3(128.91,42.67)
Net_309:
  vias: v3(128.91,36.32)
Net_312:
  vias: v3(128.91,31.24)
Net_313:
  vias: v3(128.91,28.7)
Net_314:
  vias: v3(128.91,27.43)
Net_315:
  vias: v3(128.91,24.89)
Net_316:
  vias: v3(128.91,23.62)
Net_317:
  vias: v3(128.91,21.08)
Net_318:
  vias: v3(128.91,19.81)
Net_319:
  vias: v3(128.91,17.27)
Net_320:
  vias: v3(128.91,16)
Net_321:
  vias: v3(128.91,13.46)
Net_322:
  vias: v3(128.91,12.19)
Net_323:
  vias: v3(128.91,55.37)
Net_324:
  vias: v3(128.91,9.65)
Net_327:
  vias: v3(128.91,50.29)
Net_330:
  vias: v3(127.64,57.91)
Net_333:
  vias: v3(127.64,29.97)
Net_334:
  vias: v3(127.64,28.7)
Net_335:
  vias: v3(127.64,26.16)
Net_336:
  vias: v3(127.64,24.89)
Net_338:
  vias: v3(127.64,22.35)
Net_339:
  vias: v3(127.64,21.08)
Net_340:
  vias: v3(127.64,18.54)
Net_341:
  vias: v3(127.64,17.27)
Net_342:
  vias: v3(127.64,14.73)
Net_343:
  vias: v3(127.64,13.46)
Net_344:
  vias: v3(127.64,10.92)
Net_345:
  vias: v3(126.36,59.18)
Net_346:
  vias: v3(126.36,47.75)
Net_353:
  vias: v3(126.36,31.24)
Net_354:
  vias: v3(126.36,28.7)
Net_355:
  vias: v3(126.36,27.43)
Net_356:
  vias: v3(126.36,24.89)
Net_357:
  vias: v3(126.36,23.62)
Net_358:
  vias: v3(126.36,19.81)
Net_359:
  vias: v3(126.36,17.27)
Net_360:
  vias: v3(126.36,16)
Net_361:
  vias: v3(126.36,13.46)
Net_362:
  vias: v3(126.36,12.19)
Net_364:
  vias: v3(126.36,9.65)
Net_367:
  vias: v3(126.36,50.29)
Net_378:
  vias: v3(125.09,29.97)
Net_379:
  vias: v3(125.09,28.7)
Net_380:
  vias: v3(125.09,26.16)
Net_381:
  vias: v3(125.09,24.89)
Net_383:
  vias: v3(125.09,22.35)
Net_384:
  vias: v3(125.09,21.08)
Net_385:
  vias: v3(125.09,18.54)
Net_386:
  vias: v3(125.09,17.27)
Net_387:
  vias: v3(125.09,14.73)
Net_388:
  vias: v3(125.09,13.46)
Net_391:
  vias: v3(125.09,51.56)
Net_392:
  vias: v3(125.09,49.02)
Net_393:
  vias: v3(123.83,59.18)
Net_394:
  vias: v3(123.83,47.75)
Net_404:
  vias: v3(123.83,28.7)
Net_405:
  vias: v3(123.83,27.43)
Net_406:
  vias: v3(123.83,21.08)
Net_407:
  vias: v3(123.83,19.81)
Net_408:
  vias: v3(123.83,17.27)
Net_409:
  vias: v3(123.83,16)
Net_410:
  vias: v3(123.83,55.37)
Net_411:
  vias: v3(123.83,9.65)
Net_412:
  vias: v3(123.83,54.1)
Net_414:
  vias: v3(123.83,50.29)
OSCINN: length 7.3
  BOTTOM w0.229: U3.44 81.66,62.81 81.65,62.82 81.65,63.03 82.71,64.09 83.09,64.09 83.29,63.89 83.29,63.74 83.49,63.54 83.78,63.54 83.98,63.74 83.98,63.89 84.18,64.09 85.56,64.09 C86.2
  BOTTOM w0.305: C86.2 86.6,63.83 C85.2
OSCINP: length 7.4
  BOTTOM w0.229: C83.2 85.56,64.47 82.55,64.47 81.27,63.19 81.27,62.92 81.16,62.81 U3.43
  BOTTOM w0.305: C83.2 86.63,64.74 C82.2
OSCN: length 2.6
  BOTTOM w0.305: C85.1 87.36,63.83 R82.1 R76.2 89.71,63.83 C84.2
OSCOUTN: length 3.2
  BOTTOM w0.203: C419.1 80.24,65.02 80.24,64.41 ; U3.41 80.16,62.77 80.09,62.84 80.09,64.26 80.24,64.41 ; 80.24,64.41 R180.1
OSCOUTP: length 3.3
  BOTTOM w0.203: 79.55,64.41 R181.1 ; 79.55,64.41 79.73,64.23 79.73,62.84 79.66,62.77 U3.40 ; 79.55,64.41 79.55,65.02 C418.1
OSCP: length 2.6
  BOTTOM w0.305: C82.1 87.36,64.76 R74.1 R71.2 89.72,64.76 C81.2
PDN: length 111.8
  TOP w0.127: U1.50 29.89,37.51 29.97,37.43 29.97,37.13 30.15,36.96 30.15,36.75 30.16,36.75 30.16,28.29 v1(30.18,28.27)
  L4_SIG w0.127: v1(30.18,28.27) 30.18,27.28 30.86,26.59 30.86,25.22 31.55,24.54 31.55,20.02 32.59,18.97 32.59,16.92 33.15,16.36 33.55,16.36 35.61,18.41 47.02,18.41 47.47,18.87 54.84,18.87 55.32,18.39 78.54,18.39 84.91,12.01 111.81,12.01 112.37,12.57 115.19,12.57 117.09,14.48 JP1.2
PLL2 LOCKED:
  vias: v1(58.62,55.68)
RESET: length 117.3
  TOP w0.127: v1(29.16,27.56) 29.15,37.22 28.89,37.49 U1.48
  L4_SIG w0.127: v1(29.16,27.56) 30.48,26.24 30.48,24.79 31.01,24.26 31.01,19.99 30.26,19.24 30.26,18.4 32.97,15.7 35.74,15.7 37.77,17.73 55.85,17.73 56.26,17.32 78.84,17.32 84.73,11.43 112.04,11.43 112.6,11.99 114.48,11.99 v1(119.86,6.6)
RFOUTBM: length 6.3
  TOP w0.483: J16.1 v1(40.94,53.72)
  BOTTOM w0.305: v1(40.94,53.72) 40.34,54.33 C413.2
SCAN_EN: length 1.8
  TOP w0.229: U1.49 v2(29.39,37.58) 29.54,37.43 29.54,37.21 29.67,37.08 v1(29.67,36.14)
STAT 0:
  vias: v1(61.47,55.7)
STAT 1:
  vias: v1(64.36,55.68)
SYNC: length 13.8
  TOP w0.229: TP25.1 69.32,52.55 75.97,52.55 76.99,51.54 79.92,51.54 v2(81.16,52.78)
SYNCBM: length 134.4
  TOP w0.229: U1.36 22.33,38.49 21.4,37.55 20.33,37.55 R168.1 R166.2 19.04,37.55 17.51,37.55 v1(17.28,37.32)
  BOTTOM w0.102: 127.64,43.94 127.64,44.38 127.74,44.48 128.15,44.48 128.36,44.7 128.36,45.57 127.94,45.99 123.67,45.99 123.59,46.07 123.44,46.07
  BOTTOM w0.203: v1(17.28,37.32) 16.99,37.62 16.31,37.62 15.82,37.13 15.82,36.63 16.08,36.37 16.2,36.37 16.38,36.19 16.38,35.94 16.2,35.76 16,35.76 15.82,35.58 15.82,34.47 19.94,30.35 66.45,30.35 78.64,42.55 119.77,42.55 123.3,46.07 123.44,46.07
SYNCBP: length 134.4
  TOP w0.229: U1.35 22.29,38.99 21.24,37.93 20.33,37.93 R169.1 R167.2 19.04,37.93 17.61,37.93 v1(17.28,38.27)
  BOTTOM w0.102: 123.44,45.71 123.53,45.8 127.86,45.8 128.17,45.49 128.17,44.77 128.07,44.67 127.74,44.67 127.64,44.77 127.64,45.21
  BOTTOM w0.203: v1(17.28,38.27) 16.99,37.97 16.16,37.97 15.47,37.28 15.47,34.32 19.79,30 66.59,30 78.79,42.19 119.92,42.19 123.44,45.71
SYSREF+: length 5.1
  BOTTOM w0.203: U3.13 77.66,51.94 77.59,51.87 77.59,51.58 78.55,50.62 78.55,49.31 78.75,49.11 ; R65.1 78.73,48.32 ; 78.73,49.03 R67.1
  BOTTOM w0.229: 78.73,48.32 78.73,49.08 78.75,49.11
SYSREF-: length 5.2
  BOTTOM w0.203: U3.14 77.16,51.94 77.23,51.87 77.23,51.43 78.2,50.47 78.2,49.37 77.94,49.11 ; 77.96,49.03 R68.1 ; R66.1 77.96,48.32
  BOTTOM w0.229: 77.94,49.11 77.96,49.08 77.96,48.32
SYSREFM: length 80.3
  TOP w0.229: U1.34 22.47,39.49 22.43,39.52 22.13,39.52 21.85,39.25 21.36,39.25 v1(21.2,39.09)
  BOTTOM w0.203: 78,46.69 78,46.74 77.93,46.81 ; 78,46.69 78.05,46.69 78.05,46.63 78.11,46.63 78.11,46.58 78.16,46.58 78.16,45.24 77.34,44.42 77.05,44.42 77.01,44.47 76.73,44.47 76.52,44.27 76.52,43.98 76.57,43.94 76.57,43.66 66.49,33.58 65.91,33.58 65.7,33.37 65.7,32.79 65.09,32.18 23.55,32.18 23.19,32.54 22.37,32.54 22.02,32.18 20.96,32.18 19.65,33.49 19.65,34.04 19.43,34.26 18.88,34.26 18.57,34.57 18.57,37.15 18.77,37.35 18.98,37.35 19.18,37.56 19.18,37.84 18.98,38.04 18.77,38.04 18.57,38.24 18.57,39.09 19,39.52 20.28,39.52 20.56,39.24 21.04,39.24 v1(21.2,39.09) ; 78,46.69 R69.1 77.91,46.85 77.93,46.85 ; R66.2 77.96,47.61
  BOTTOM w0.229: 77.96,47.61 77.96,46.85 77.93,46.85 77.93,46.81
SYSREFP: length 80.3
  TOP w0.229: U1.33 22.48,39.99 22.4,39.9 21.97,39.9 21.69,39.63 21.37,39.63 v1(21.2,39.8)
  BOTTOM w0.203: v1(21.2,39.8) 21,39.6 20.7,39.6 20.41,39.89 20.31,39.89 20.3,39.9 18.84,39.9 18.19,39.25 18.19,34.42 20.8,31.8 22.17,31.8 22.38,32 23.22,32 23.39,31.83 65.24,31.83 78.54,45.12 78.54,46.58 ; 78.77,46.85 78.78,46.85 R70.1 78.59,46.58 78.54,46.58 ; 78.54,46.58 78.77,46.81 ; R65.2 78.73,47.61
  BOTTOM w0.229: 78.77,46.81 78.77,46.85 78.73,46.85 78.73,47.61
VCM: length 9.1
  TOP w0.254: 20.38,45.49 U1.22
  TOP w0.305: 20.38,45.49 18.29,47.57 C61.1 16.89,49.07 TP2.1
Y2_N: length 13.9
  BOTTOM w0.229: R81.1 93.04,64.11 93.8,64.11 94.39,63.52 94.39,58.82 95.21,58 95.95,58 96.35,57.6 96.35,57.15 96.57,56.92 Y1.4
  BOTTOM w0.305: R81.1 92,63.83 R80.1
Y2_P: length 13.8
  BOTTOM w0.229: R73.1 93.04,64.49 93.95,64.49 94.77,63.68 94.77,58.98 95.36,58.38 95.92,58.38 96.35,58.8 96.35,59.23 96.57,59.46 Y1.5
  BOTTOM w0.305: R73.1 92,64.77 R72.1
YO2_N: length 0.9
  BOTTOM w0.305: C84.1 R80.2
YO2_P: length 0.9
  BOTTOM w0.305: C81.1 R72.2
N851442: length 3.9
  TOP w0.483: C414.2 15.14,26.27 C424.2 15.45,26.62 15.84,26.62 T1.6 16.62,27.44 R1.1
N16260551: length 3.8
  TOP w0.483: 16.54,62.07 16.54,62.07 C426.2 17.58,61.03 17.58,60.67 T3.6 R13.1
N17912008: length 3.8
  TOP w0.483: 16.54,23.35 17.32,24.13 C425.2 17.58,24.39 17.58,24.77 T1.4 R11.1
N18340257: length 2.7
  BOTTOM w0.305: v1(40.11,4.57) 38.86,5.82 R133.2
N19112270: length 3.7
  TOP w0.483: 15.21,59.16 15.49,58.88 15.78,58.88 T3.4 16.66,58.03 R23.1 ; 15.21,59.16 C427.2 ; 15.21,59.16 14.46,59.92
N19631466: length 1.6
  TOP w0.305: v1(108.14,5.15) 108.14,5.98 C166.1
  BOTTOM w0.305: U12.14 v1(108.14,5.15)
N19631491: length 1.7
  TOP w0.305: R127.2 111.15,8.33 v1(111.99,8.33)
  BOTTOM w0.305: U12.8 v1(111.99,8.33)
N19631493: length 1.7
  TOP w0.305: R125.2 110.09,5.69 v1(110.09,5.16)
  BOTTOM w0.305: U12.11 v1(110.09,5.16)
N19631495: length 1.7
  TOP w0.305: R124.2 109.44,5.83 v1(109.44,5.15)
  BOTTOM w0.305: U12.12 v1(109.44,5.15)
N19631505: length 1.5
  TOP w0.305: v1(112.07,7.03) 111.53,7.03 R126.2
  BOTTOM w0.305: U12.10 v1(112.07,7.03)
N19879103: length 22.9
  BOTTOM w0.203: C104.1 16.85,12.94
  BOTTOM w0.229: C104.1 16.22,12.94 13.63,12.94 10.13,9.44 9.68,9.44 9.47,9.65 J11.3 ; U5.15 25.01,14.27 25.14,14.4 25.85,14.4 26.08,14.17 26.08,13.23 25.79,12.94 16.85,12.94
N19879131: length 4.2
  BOTTOM w0.305: J11.4 4.2,10.45 v1(3.99,10.24)
N19879145: length 1.6
  BOTTOM w0.483: J11.1 v1(9.68,8.05)
  vias: v1(7.19,8.05) v1(8.08,8.05) v1(8.97,8.05) v1(18.67,14.58) v1(18.67,13.92) v1(19.35,14.25) v1(20.04,14.58) v1(20.04,13.92)
N19879149: length 24.1
  BOTTOM w0.229: U5.16 25.04,14.92 25.17,14.78 26.01,14.78 26.46,14.33 26.46,13.08 25.95,12.56 16.85,12.56 C103.1 16.22,12.56 13.79,12.56 10.29,9.06 9.65,9.06 9.44,8.85 J11.2
N19879167: length 14.5
  TOP w0.508: v1(25.83,17.45) 28.03,17.45 C101.1
  BOTTOM w0.381: 25.77,17.52 v1(25.83,17.45) ; R95.2 21.53,17.52
  BOTTOM w0.432: 19.69,18.44 TP4.1 ; TP4.1 21.51,18.44 ; TP4.1 19.38,19.35 ; TP4.1 20.6,18.14 ; TP4.1 20.6,20.57 ; TP4.1 19.69,20.27
  BOTTOM w0.508: 21.53,17.52 U5.20 25.77,17.52
N19879302: length 10.4
  TOP w0.127: v1(34.1,16.22) 34.1,21.71 v1(34.78,22.38)
  BOTTOM w0.127: U29.10 v1(34.78,22.38) ; U5.11 v1(34.1,16.22)
N19879304: length 5.4
  TOP w0.127: v1(32.72,21.42) 34.25,22.94 v1(34.25,23.03)
  BOTTOM w0.127: U29.11 v1(34.25,23.03) ; U5.3 v1(32.72,21.42)
N19881704: length 14.5
  L4_SIG w0.127: v1(121.72,29.24) 121.97,29.24 125.17,32.44 126.26,32.44 131.42,37.59 v3(132.72,37.59)
N19881714: length 0.4
  TOP w0.127: v3(126.36,57.91) 126.34,57.91 R89.1
N19881723: length 1.5
  TOP w0.127: D5.1 118.64,29.24 R88.1
N19884870:
  vias: v1(96.95,62.74) v1(96.95,61.87) v1(97.51,62.31) v1(98.07,62.74) v1(98.09,61.87) v1(99.01,62.79) v1(99.97,62.71) v1(101.09,62.69) v1(102.23,62.71)
N19884947:
  vias: v1(104.67,58.67)
N19886018: length 4.1
  BOTTOM w0.203: R64.1 75.9,50.16 75.9,50.88 76.23,51.21 76.23,51.87 76.16,51.94 U3.16
  BOTTOM w0.229: C9.1 75.67,49.8 R64.1
N19886020: length 4.1
  BOTTOM w0.203: R63.1 76.25,50.13 76.25,50.73 76.59,51.06 76.59,51.87 76.66,51.94 U3.15
  BOTTOM w0.229: R63.1 76.43,49.78 C8.1
N19887754: length 2.3
  TOP w0.381: v1(80.67,63.53) 80.21,63.53 FB8.2
  BOTTOM w0.305: v1(80.67,63.53) 80.66,63.52 U3.42
N19887756:
  vias: v2(83.16,62.28) v2(83.16,61.93) v2(83.16,61.57)
N19887760:
  vias: v2(84.15,59.11) v2(84.49,59.11) v2(84.84,59.13)
N19887762:
  vias: v2(84.12,53.59) v2(84.49,53.6) v2(84.86,53.59)
N19887789: length 22.7
  L4_SIG w0.127: v1(74.37,60.48) 74.23,60.62 69.28,60.62 68.68,60.02 68.2,60.02 68.02,60.2 67.26,60.2 65.41,58.34 62,58.34 61.54,57.89 61.54,57.64 58.45,54.55 58.44,54.55 58.18,54.29 58.18,54.27 57.98,54.08 v1(55.78,54.08)
  BOTTOM w0.127: U3.31 74.5,60.61 v1(74.37,60.48)
N19887795: length 33.6
  L4_SIG w0.127: v1(58.62,54.1) 60.79,56.27 69.84,56.27 70.97,57.4 75.79,57.4 76.21,57.82 84.32,57.82 85.18,58.69 85.18,61.79 v1(85.03,61.93)
  BOTTOM w0.127: U3.48 83.66,62.2 83.79,62.33 84.63,62.33 v1(85.03,61.93)
N19887804: length 24.8
  L4_SIG w0.127: v1(64.36,54.1) 64.85,54.58 70.48,54.58 72.22,56.32 75.76,56.32 76.21,55.87 86,55.87 v1(86.24,56.1)
  BOTTOM w0.127: U3.59 v1(86.24,56.1)
N19887822: length 26.4
  L4_SIG w0.127: v1(85.56,56.6) 85.29,56.87 72.26,56.87 70.43,55.04 62.38,55.04 v1(61.47,54.13)
  BOTTOM w0.127: U3.58 v1(85.56,56.6)
N19887828: length 1.9
  TOP w0.381: C96.1 77.24,52.83 77.93,52.15 v1(78.16,52.15)
  BOTTOM w0.305: U3.12 v1(78.16,52.15)
N19887830: length 1
  TOP w0.254: 78.6,53.07 78.66,53.01 v2(78.66,52.43) ; 78.6,53.07 C97.1 ; 78.6,53.07 v2(78.66,53.14)
  vias: v2(78.66,52.78)
N19887836: length 3.3
  TOP w0.254: 79.4,52.91 v2(79.17,53.14) 79.17,52.79 ; 79.17,52.45 79.17,52.76 v2(79.16,52.78)
  TOP w0.305: C88.2 v2(79.15,52.43) 79.63,52.73 C88.2 ; C88.2 79.29,52.91 v2(79.16,52.78)
  BOTTOM w0.305: v2(79.16,52.78) v2(79.15,52.43)
  vias: v2(76.15,62.28) v2(76.15,61.57) v2(76.16,61.93) v2(77.65,62.28) v2(77.65,61.57) v2(77.66,61.93)
N19887876: length 1.9
  BOTTOM w0.305: U3.39 79.16,63.31 v1(78.79,63.68)
N19887878: length 1.8
  TOP w0.305: v1(82.16,62.78) 82.16,63.62 FB9.2
  BOTTOM w0.305: U3.45 v1(82.16,62.78)
N19887910: length 1.3
  BOTTOM w0.305: v1(74.35,55.6) v2(75.01,55.6) v2(75.62,55.6)
N19887912: length 1.5
  BOTTOM w0.305: v2(75.49,53.59) 75.06,53.59 v2(75.03,53.62) 74.07,53.62 v1(74.04,53.59)
N19887930: length 1.6
  BOTTOM w0.305: U3.26 74.39,58.11 v1(74.35,58.06) ; v2(75.54,58.12) v2(74.98,58.12)
N19893167: length 3.1
  TOP w0.483: C372.1 12.74,43.94 v1(12.73,43.93)
N19893194: length 3.1
  TOP w0.483: v1(12.73,41.39) 12.74,41.4 C373.1
N19893222: length 2
  BOTTOM w0.483: C28.2 7.06,43.93 T5.4
N19893438: length 1.6
  BOTTOM w0.483: T5.2 12.21,42.67 v1(10.67,42.67)
N19895463: length 1.3
  TOP w0.229: U32.4 17.65,43.94 C372.2
N19895477: length 1.3
  TOP w0.229: U33.4 17.59,41.4 C373.2
N19955835: length 0.8
  BOTTOM w0.508: v1(31.93,5.44) 31.93,5.66 U15.4
N20015888: length 34.6
  BOTTOM w0.229: J13.1 115.54,57.99 115.24,57.68 112.75,57.68 109.57,54.51 94.54,54.51 90.56,58.49 89.11,58.49 C170.2
N20015984: length 34.8
  BOTTOM w0.229: J14.1 115.54,56.97 115.21,57.3 112.9,57.3 109.73,54.13 94.38,54.13 90.4,58.11 89.07,58.11 C171.2
N20042801: length 1.7
  BOTTOM w0.305: R139.2 56.44,17.86 U16.7
N20043120: length 1.9
  BOTTOM w0.305: U16.6 56.11,18.51 R138.2
N20043460: length 1.7
  BOTTOM w0.305: U16.9 56.47,16.56 R140.2
N20043630: length 1.9
  BOTTOM w0.305: R141.2 56.11,15.91 U16.10
N20048856: length 1.7
  BOTTOM w0.305: R137.2 53.09,21.33 U16.4
N20080651: length 11.6
  TOP w0.508: v1(41.84,24.98) 41.57,24.98 40.34,26.21 SJP5.2
  BOTTOM w0.305: U29.8 37.18,21.08 37.59,21.49 37.59,23.83 38.75,24.98 v1(41.84,24.98)
N20101312: length 2.6
  TOP w0.305: R134.1 R132.2 44.62,3.7 U14.3
N20101314: length 16.6
  TOP w0.381: 44.37,9.75 43.94,10.41 43.94,11.48 44.31,12.36 ; 44.37,9.75 44.14,10.25 44.14,12.18 44.31,12.36 ; 44.37,9.75 44.7,10.31 44.7,11.51 44.31,12.36 ; 44.37,9.75 U14.6 ; 44.37,9.75 44.45,10.69 44.31,12.36 ; 44.37,9.75 44.37,12.38 L1.1
N20101373: length 2.9
  L6_PWR w0.305: v1(46.68,4.7) 46.27,5.11 44.88,5.11 44.5,4.72 v2(44.12,4.72)
  vias: v2(44.12,5.46) v2(44.12,5.08)
N20111831: length 2.6
  TOP w0.305: R155.1 R154.2 U11.3
N20111833: length 13.4
  TOP w0.381: 59.43,10.36 59.16,11.04 59.16,11.75 L2.1 ; 59.43,10.36 59.43,12.64 L2.1 ; 59.43,10.36 59.43,9.78 ; L2.1 59.87,11.64 59.87,10.79 59.69,10.39 ; L2.1 59.69,10.39 ; 59.43,9.78 59.69,10.39 ; 59.43,9.78 U11.6
N20111884: length 4.3
  TOP w0.305: U11.2 v1(59.18,4.8)
  L6_PWR w0.305: v1(62.03,4.85) 61.24,5.64 60.02,5.64 v1(59.18,4.8)
N20113515: length 4.2
  BOTTOM w0.381: R145.1 R143.2 ; R143.2 75.74,14.25 75.59,14.41 U17.16 ; R143.2 77.55,14.25 C193.2
N20114896: length 2.9
  TOP w0.305: U18.4 84.08,6.06 v1(84.23,5.92)
  TOP w0.508: v1(84.23,5.92) 84.23,5.79 v1(84.61,5.41) v1(85.75,5.41)
  vias: v1(85.5,15.57) v1(85.5,14.81) v1(85.45,14.05) v1(85.5,13.28) v1(85.5,12.52) v1(86.21,14.05) v1(86.26,15.57) v1(86.26,14.81) v1(86.26,13.28) v1(86.26,12.52) v1(87.15,15.57) v1(87.15,14.81) v1(87.1,14.05) v1(87.15,13.28) v1(87.15,12.52)
N20114915: length 2.7
  TOP w0.305: R147.1 R146.2 83.58,5.42 U18.3
N20114917: length 20.8
  TOP w0.305: L3.1 83.69,12.78 83.67,12.06 ; L3.1 83.33,13.97 83.33,11.07 ; L3.1 82.83,12.85 82.8,12.6 82.93,12.12 ; L3.1 83.13,11.6 ; L3.1 83.67,12.06 ; L3.1 82.93,12.12 ; L3.1 83.42,11.32 ; 83.33,11.07 83.42,11.32 ; 83.33,11.07 U18.6 ; 83.33,11.07 83.13,11.6 ; 83.42,11.32 83.67,12.06 ; 82.93,12.12 83.13,11.6
N20114968: length 4.3
  TOP w0.305: U18.2 83.08,6.2 v1(82.83,5.94)
  L6_PWR w0.305: v1(82.83,5.94) 83.44,6.55 85.62,6.55 v1(85.75,6.43)
N20150497:
  vias: v1(51.79,15.04)
N20151052:
  vias: v1(70.63,15.71)
N20152729: length 2.1
  TOP w0.305: SJP4.2 81.81,5.79 82.58,6.56 U18.1
N20210385: length 61.4
  TOP w0.229: v1(20.15,50.12) 21.18,49.08 21.18,47.12 21.82,46.49 U1.20
  L4_SIG w0.127: TP32.1 62.31,27.69 58.93,27.69 57.32,29.3 57.32,29.5 57.05,29.76 56.81,29.76 48.87,37.69 48.87,38.4 40.84,46.43 40.1,46.43 34.64,51.89 27.88,51.89 27.24,52.54 25.9,52.54 25.25,51.89 24.46,51.89 22.35,49.78 20.86,49.78 20.53,50.12 v1(20.15,50.12)
  BOTTOM w0.229: v1(20.15,50.12) 19.69,50.57 R165.2
N20210389: length 68.9
  TOP w0.229: U1.21 22.07,45.99 22.01,46.05 21.57,46.05 20.65,46.96 20.65,48.69 19.73,49.61 v1(19.64,49.61)
  L4_SIG w0.127: v1(19.64,49.61) 19.64,50.24 20.23,50.83 21.06,50.83 21.09,50.79 21.14,50.79 21.51,50.42 22.48,50.42 24.69,52.63 25.04,52.63 26.09,53.67 26.8,53.67 27.84,52.63 34.6,52.63 38.79,48.44 39.59,48.44 40.83,47.2 40.83,47.19 47.11,40.91 47.25,40.91 54.9,33.25 54.9,32.4 56.64,30.67 56.65,30.67 59.21,28.12 66.95,28.12 TP33.1
  BOTTOM w0.229: R164.2 19.15,50.11 v1(19.64,49.61)
N20213760:
  vias: v1(114.45,6.73)
N20220794:
  vias: v1(94.61,18.16) v1(94.61,17.14) v1(94.61,16.13) v1(95.5,18.16) v1(95.5,17.14) v1(95.5,16.13) v1(96.39,18.16) v1(96.39,17.14) v1(96.39,16.13)
N20220969: length 1.4
  TOP w0.305: C387.1 95.46,7.18 v1(95.46,6.44)
  BOTTOM w0.305: U31.14 v1(95.46,6.44)
N20220990: length 1.5
  TOP w0.305: R171.2 98.48,9.53 v1(99.24,9.53)
  BOTTOM w0.305: U31.8 v1(99.24,9.53)
N20220992: length 1.4
  TOP w0.305: v1(97.71,6.5) R172.2
  BOTTOM w0.305: U31.11 97.41,6.8 v1(97.71,6.5)
N20220994: length 1.7
  TOP w0.305: R170.2 96.76,7.02 v1(96.76,6.36)
  BOTTOM w0.305: U31.12 v1(96.76,6.36)
N20221006: length 1.2
  TOP w0.305: v1(98.78,7.72) R173.2
  BOTTOM w0.305: U31.10 98.68,8.23 98.78,8.13 v1(98.78,7.72)
N20227487: length 2.6
  BOTTOM w0.305: U30.27 39.39,62.19 39.3,62.28 38.76,62.28 C400.2 38.13,62.2 v1(38.13,62.18)
N20231187: length 2.4
  BOTTOM w0.305: U30.3 48.58,62.69 C403.2
N20232417: length 1
  BOTTOM w0.305: v1(44.68,65.51) 44.66,65.49 U30.38
N20232915: length 1.4
  BOTTOM w0.305: v1(39.04,63.27) 39.12,63.19 U30.29
N20233092: length 2.9
  TOP w0.305: v1(43.74,65.61) 43.56,65.79 C406.2 v2(43.56,65.99)
  BOTTOM w0.305: U30.36 43.66,65.6 ; 43.66,65.6 43.66,65.61 v1(43.74,65.61) ; 43.66,65.6 43.66,65.89 ; v1(43.74,65.61) 43.74,65.81 43.66,65.89 ; v1(43.74,65.61) 43.56,65.79 v2(43.56,65.99) 43.66,65.89
N20234062: length 0.9
  TOP w0.305: v2(42.16,64.11) 42.16,64.34 C407.2 41.96,64.64 v2(42.16,64.85)
  vias: v2(42.16,64.47)
N20235277: length 7.2
  BOTTOM w0.229: U30.23 39.71,60.19 R175.1 37.04,60.08 34.56,60.08 C409.1
N20235286: length 7.2
  BOTTOM w0.229: U30.22 39.7,59.69 R176.1 37.15,59.7 34.48,59.7 C410.1
N20237052: length 3.9
  BOTTOM w0.229: U30.18 42.15,58.41 42.15,57.43 43.22,56.36 R177.1 C412.1
N20237066: length 3.9
  BOTTOM w0.229: C413.1 R178.1 41.66,57.51 U30.19
N20239082: length 2.2
  BOTTOM w0.127: R179.2 39.12,64.21 39.63,63.69 U30.30
N20249678: length 1.1
  TOP w0.305: 46.25,59.18 v2(46.08,59.18) ; 46.25,59.18 46.2,59.23 46.41,59.23 v2(46.46,59.18) ; 46.25,59.18 v2(46.46,59.18) ; v2(46.46,59.18) v2(46.79,59.18)
N20251064: length 1.5
  BOTTOM w0.229: C394.2 R174.1 ; 51.44,66.32 51.44,67.08
N20251377: length 1.7
  BOTTOM w0.229: R182.2 R183.1 C420.1
N20251505: length 5.8
  BOTTOM w0.229: U30.35 43.16,65.27 43.1,65.33 43.1,66.22 43.33,66.45 46.08,66.45 C421.1 46.2,66.32 R183.2
N20257347: length 15.5
  L4_SIG w0.127: v1(39.09,56.36) 39.12,56.33 40.18,56.33 41.27,57.43 41.27,63.35 41.68,63.75 41.68,65.38 v1(40.56,66.5)
  BOTTOM w0.127: v1(39.09,56.36) 39.45,56.36 41.16,58.08 U30.20
N20258125:
  vias: v1(39.85,66.5)
N20306930: length 1.4
  TOP w0.229: C429.1 18.9,43.28 18.9,43.75 18.67,43.98 U32.6
N20306944: length 1.5
  TOP w0.229: C430.1 18.92,42.09 18.92,41.54 18.69,41.31 U33.6
N198851401: length 0.9
  BOTTOM w0.305: C71.2 R54.1
N198852420: length 1
  BOTTOM w0.305: C70.2 72.24,60.22 R47.1

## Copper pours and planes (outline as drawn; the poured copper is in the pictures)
1.4V on TOP: 61.77,8.66 61.77,10.67 61.37,11.07 61.37,14.5 63.55,14.5 64.31,13.74 64.31,9.17 63.8,8.66
1.4V on BOTTOM: 61.39,9.98 61.39,14.83 67.59,14.83 67.59,16.33 69.9,16.33 69.9,11.07 70.79,11.07 70.79,9.86 69.57,8.64 62.74,8.64
5.0V_IN on TOP (solid shape): 32.31,6.85 27.79,6.85 27.79,10.66 32.31,10.66
5.0V_IN on TOP: 17.2,6.43 17.2,9.35 19.13,11.28 32.28,11.28 33.07,10.49 33.07,7.06 32.44,6.43 24.18,6.43 22.91,5.16 18.47,5.16
5.0V_IN on BOTTOM: 17.2,6.43 17.2,9.37 19.1,11.28 32.28,11.28 33.07,10.49 33.07,7.06 32.66,6.65 24.41,6.65 22.91,5.16 18.47,5.16
5VIN on TOP: 43.81,9.78 43.81,4.65 42.19,4.65 42.19,9.78
5VIN on TOP: 82.83,11.63 82.83,7.82 80.92,7.82 80.54,8.2 80.54,11.25 80.92,11.63
5VIN on TOP: 35.61,5.13 35.61,3.25 38.79,3.25 38.79,5.13
5VIN on TOP: 58.98,10.19 58.98,5.05 57.35,5.05 57.35,10.19
5VIN on TOP, BOTTOM: 27.61,5.79 27.61,2.87 31.04,2.87 31.04,5.79
5VIN on BOTTOM: 35.86,3.51 35.86,5.16 38.28,5.16 38.28,3.51
5VIN on BOTTOM: 20.6,16.31 20.6,15.04 22.45,15.04 22.45,16.31
5VIN on BOTTOM: 58.65,9.8 58.65,5.11 57.33,5.11 57.33,9.8
5VIN on BOTTOM: 43.56,9.4 43.56,4.7 42.16,4.7 42.16,9.4
5VIN on BOTTOM: 103.53,5.61 103.53,6.35 104.04,6.35 104.9,7.21 106.86,7.21 106.86,6.35 108.99,6.35 108.99,4.34 108.51,3.86 105.28,3.86
5VIN on BOTTOM: 90.86,6.93 90.86,8.53 94.18,8.53 94.18,7.67 96.32,7.67 96.32,5.66 95.83,5.18 92.61,5.18
5VIN on BOTTOM: 82.58,11.25 82.58,8.08 80.54,8.08 80.54,11.25
5VIN on L3_PWR: 15.24,1.91 15.24,16.26 81.53,16.26 86.36,11.43 106.68,11.43 106.68,1.91
+2.2V on TOP: 48.51,4.83 48.51,8.26 46.23,8.26 46.23,15.32 51.18,15.32 51.18,13.08 51.82,12.45 51.82,4.83
+2.2V on BOTTOM: 46.1,14.71 46.1,10.79 48.51,8.38 51.94,8.38 51.94,10.92 51.31,11.56 51.31,15.37 50.67,15.37 50.67,16.69 48.08,16.69
+3.3V_LMX on TOP: 102.11,19.43 102.11,27.05 97.54,27.05 97.41,26.92 97.41,22.35 100.33,19.43
+3.3V_LMX on TOP: 43.03,63.6 43.03,65.23 44.88,65.23 44.88,63.6
+3.3V_LMX on L3_PWR: 97.46,21.59 97.46,31.11 69.85,31.11 42.55,58.42 40.51,58.42 39.62,59.31 39.62,66.04 50.8,66.04 75.56,41.27 106.05,41.27 106.05,21.59
+3.3V_LMXRF on TOP: 94.23,19.56 94.23,25.65 96.65,25.65 96.65,19.56
+3.3V_LMXRF on BOTTOM: 23.75,61.11 23.75,62.51 25.65,62.51 25.65,61.11
+3.3V_LMXRF on L3_PWR: 96.62,19.05 96.62,29.84 69.22,29.84 41.91,57.15 40.64,57.15 38.99,58.8 38.99,66.04 23.5,66.04 23.5,59.05 63.5,19.05
+3.3VCLK on TOP: 73.15,58.93 73.15,55.12 72.9,54.86 72.9,53.24 72.85,53.19 71.55,53.19 71.55,54.36 71.91,54.71 71.91,58.93
+3.3VCLK on TOP: 111.3,24.84 111.3,18.31 115.8,18.31 115.8,24.84
+3.3VCLK on TOP: 77.95,64.52 76.28,64.52 76.28,66.14 77.09,66.95 77.95,66.95
+3.3VCLK on TOP: 86.92,53.21 86.92,51.56 88.06,51.56 88.06,53.21
+3.3VCLK on TOP: 85.62,59.75 85.62,61.19 85.85,61.42 86.92,61.42 86.92,59.75
+3.3VCLK on BOTTOM: 110.87,17.91 110.87,19.3 111.12,19.56 111.12,24.51 114.05,24.51 115.54,23.01 115.54,20.29 113.16,17.91
+3.3VCLK on L6_PWR: 107.31,19.96 107.31,46.1 103.25,50.16 62.66,50.16 62.66,66.67 109.86,66.67 121.28,55.24 121.28,16.51 110.77,16.51
AVDD1.9V on TOP: 47.47,24.71 47.47,21.49 52.88,21.49 52.88,24.94 49.78,24.94 49.56,24.71
AVDD1.9V on BOTTOM: 47.24,19.68 47.24,20.83 47.52,21.11 47.52,24.66 49.05,24.66 49.4,25.02 52.07,25.02 52.45,24.64 52.45,21.08 51.94,20.57 51.94,19.05 50.55,19.05 50.55,17.65 49.28,17.65
AVDD1.9V on L3_PWR: 9.53,26.04 9.53,41.27 15.37,47.12 20.95,47.12 20.95,51.44 28.57,51.44 28.57,33.66 20.95,33.66 20.95,35.56 19.68,35.56 19.05,34.92 19.05,30.48 24.13,25.4 52.93,25.4 52.93,17.14 18.41,17.14
AVDD1.15V on BOTTOM: 74.86,21.24 68.17,21.24 68.17,24.92 71.22,24.92 71.22,24.03 71.68,23.57 78.03,23.57 78.03,21.23 74.85,21.23
AVDD1.15V on L6_PWR: 9.53,26.04 9.53,41.27 15.24,46.99 20.95,46.99 20.95,51.44 28.32,51.44 28.32,39.12 28.07,38.86 28.07,33.66 20.95,33.66 20.95,37.41 19.63,37.41 19.05,36.83 19.05,30.48 24.51,25.02 72.01,25.02 72.01,17.14 18.41,17.14
DVDD1.15V on TOP: 88.57,18.26 88.57,21.01 85.88,23.7 83.97,23.7 82.7,22.43 82.7,19.28 83.72,18.26
DVDD1.15V on TOP: 39.55,27.58 39.55,26.29 38.25,26.29 38.25,27.86 39.27,27.86
DVDD1.15V on BOTTOM: 83.19,17.93 83.19,23.27 86.44,23.27 86.44,17.93
DVDD1.15V on L6_PWR: 66.55,34.92 44.45,34.92 44.45,26.42 32.64,26.42 28.96,30.1 28.96,35.43 28.45,35.94 28.45,37.85 28.96,38.35 28.96,47.47 28.7,47.75 28.7,51.44 44.45,51.44 44.45,46.35 72.42,46.35 88.9,29.87 88.9,18.16 77.47,18.16 77.47,24
GND on TOP: 0.25,68.33 0.25,0.25 139.45,0.25 139.45,68.33 ; 3 cut-outs
GND on BOTTOM: 0.25,68.33 0.25,0.25 139.45,0.25 139.45,68.33 ; 11 cut-outs
GND on L2_GND, L3_PWR, L4_SIG, L5_GND, L6_PWR, L7_GND: 0.25,68.33 0.25,0.25 139.45,0.25 139.45,68.33
AINM on TOP (solid shape): 25.51,38 25.5,37.66 25.58,36.42 25.58,36.2 24.94,36.2 24.94,36.41 24.98,36.6 25.26,37.67 25.26,38.01
AINP on TOP (solid shape): 26.01,37.68 26.45,36.57 26.45,36.19 25.82,36.19 25.82,36.55 25.76,37.67 25.76,38 26,38
BINM on TOP (solid shape): 25.76,49.15 25.5,47.85 25.5,47.48 25.27,47.48 25.27,47.9 25.14,49.09 25.13,49.63 25.77,49.63
BINP on TOP (solid shape): 26.65,49.47 26.65,48.99 26.64,48.93 26.43,48.56 26.01,47.86 26,47.47 25.77,47.47 25.77,47.84 25.89,48.47 26.02,49.05 26.02,49.47
U17_BYPASS on BOTTOM: 60.88,15.39 60.88,17.81 62.66,19.58 73.2,19.58 73.2,17.42 63.93,17.42 63.3,16.79 63.3,15.39
N19631315 on BOTTOM: 105.03,9.53 105.03,12.19 106.68,12.19 106.93,12.45 106.93,16.89 111.25,16.89 111.63,16.51 112.65,16.51 112.65,13.97 109.73,13.97 109.22,13.46 109.22,10.16 106.93,10.16 106.93,9.53
N19879145 on TOP: 6.91,7.52 6.91,8.02 13.88,14.94 20.37,14.94 20.37,12.62 15.06,12.62 9.96,7.52
N19879167 on BOTTOM: 22.02,17.14 22.02,19.84 21.06,20.8 19.46,20.8 18.39,19.74 18.39,17.14
N19887756 on TOP: 78.36,64.87 78.36,66.83 82.88,66.83 82.88,66.62 84.2,65.28 84.2,61.52 84.1,61.42 83.11,61.42 83.01,61.52 83.01,64.49 82.68,64.82 78.41,64.82
